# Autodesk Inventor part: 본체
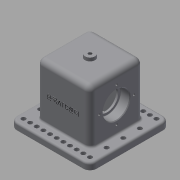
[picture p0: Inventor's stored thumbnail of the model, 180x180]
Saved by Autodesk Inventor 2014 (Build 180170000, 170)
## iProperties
Created: 2018-11
Part Number: 본체
Material: Generic
Document SubType Name: Modeling
Designer: kh
Density: 1 g/cm^3
Appearance: Default
Author: kh
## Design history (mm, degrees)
sketch "스케치1"
  geometry: L1 (60, 60)-(-60, 60); L2 (-60, 60)-(-60, -60); L3 (-60, -60)-(60, -60); L4 (60, -60)-(60, 60); L5 (60, 60)-(-60, -60); L6 (-60, 60)-(60, -60); 1 further point
  constraints: 12 end point, 2 midpoint, 2 parallel, 1 horizontal, 1 perpendicular
  dimensions: "d0" = 120 distance of L3.end L2.end; "d1" = 120 distance of L2.end L1.end
extrude "돌출1" new body sketch "스케치1" distance "d2" = 10; taper "d3" = 0 deg
sketch "스케치2"
  geometry: L1 (-40, -40)-(40, -40); L2 (40, -40)-(40, 40); L3 (40, 40)-(-40, 40); L4 (-40, 40)-(-40, -40); L5 (-40, -40)-(40, 40); L6 (40, -40)-(-40, 40); 1 further point
  constraints: 12 end point, 2 midpoint, 2 parallel, 1 horizontal, 1 perpendicular
  dimensions: "d4" = 80 distance of L3.end L2.end; "d5" = 80 distance of L2.end L1.end
extrude "돌출2" join sketch "스케치2" distance "d6" = 80; taper "d7" = 0 deg
sketch "스케치3"
  geometry: L1 (-23, -30)-(23, -30); L2 (23, -30)-(23, 30); L3 (23, 30)-(-23, 30); L4 (-23, 30)-(-23, -30); L5 (-23, -30)-(23, 30); L6 (23, -30)-(-23, 30); 1 further point
  constraints: 12 end point, 2 midpoint, 2 parallel, 1 horizontal, 1 perpendicular
  dimensions: "d8" = 46 distance of L3.end L2.end; "d9" = 60 distance of L2.end L1.end
extrude "돌출3" cut sketch "스케치3" distance "d10" = 80; taper "d11" = 0 deg
sketch "스케치4"
  geometry: L1 (23, 0)-(-23, 0) reference; L2 (-23, 0)-(23, 0) reference; L3 (-60, 0)-(60, 0) reference; L4 (60, 0)-(-60, 0) reference; L5 (-40, 90)-(40, 90) reference; L6 (40, 90)-(-40, 90) reference; L7 (-40, 48)-(40, 48); L8 (40, 68)-(26, 68); L9 (26, 68)-(26, 64.5); L10 (23, 0)-(23, 80) reference; L11 (23, 0)-(23, 80) reference; L12 (26, 64.5)-(23, 64.5); L13 (40, 68)-(40, 48); L14 (23, 64.5)-(23, 48); 1 further point
  constraints: 12 end point, 3 perpendicular, 3 point on line, 2 parallel
  dimensions: "d12" = 48 distance between parallel lines of L1 L7; "d13" = 33 diameter of L12 L7; "d14" = 40 diameter of L8 L7; "d15" = 14 distance of L8.start L8.end; "d16" = 3 distance of L9.end L12.end
revolve "회전1" sketch "스케치4" stored, may be unused: angle "d17" = 90 deg
node "작업 평면1"
sketch "스케치5"
  geometry: C1 r 7.5 at (0, 0); 2 further points
  constraints: 2 coincident, 1 centre point
  dimensions: "d19" = 15 diameter of C1
extrude "돌출4" join sketch "스케치5" stored distance "d20" = 80; taper "d21" = 0 deg
hole "구멍1" diameter "d24" = 4.917; stored, may be unused: countersink angle "d28" = 90 deg, drill point angle "d30" = 118 deg; dims "d25" = 20, "d26" = 4, "d27" = 2, "d29" = 8, "d71" = 10, "d72" = 10
sketch "스케치6"
  geometry: L1 (40, 64)-(40, 12); L2 (66, 38)-(14, 38); C1 r 20 at (40, 38) reference; A1 r 26 centre (40, 38) between (40, 64) and (40, 12); 7 further points
  constraints: 7 coincident, 4 end point, 4 point on circle, 2 midpoint, 1 centre point, 1 perpendicular, 1 vertical
  dimensions: "d31" = 52 diameter of A1
hole "구멍2" sketch "스케치6" at (40, 64), (14, 38), (40, 12), (66, 38) diameter "d32" = 3.242; stored, may be unused: countersink angle "d36" = 90 deg, drill point angle "d38" = 118 deg; dims "d33" = 8, "d34" = 4, "d35" = 2, "d37" = 10
fillet "모깎기1" dims "d39" = 10
sketch "스케치7"
  geometry: C1 r 3.3 at (50, -50); C2 r 3.3 at (-50, 50); A1 r 10 centre (50, -50) between (50, -60) and (60, -50) reference; A2 r 10 centre (-50, 50) between (-50, 60) and (-60, 50) reference; 1 further point
  constraints: 2 centre point, 2 coincident
  dimensions: "d40" = 6.6 diameter of C1; "d52" = 6.6 diameter of C2
extrude "돌출5" cut sketch "스케치7" stored distance "d41" = 80; taper "d42" = 0 deg
extrude "돌출6" cut sketch "스케치7" stored distance "d53" = 80; taper "d54" = 0 deg
fillet "모깎기2" dims "d61" = 8
fillet "모깎기3" dims "d62" = 0.6
chamfer "모따기1" distance "d63" = 1; stored, may be unused: second distance "d64" = 2, angle "d65" = 45 deg
fillet "모깎기5" dims "d67" = 3
node "작업 평면3"
fillet "모깎기6" dims "d73" = 8
fillet "모깎기7" dims "d74" = 3
sketch "스케치8"
  geometry: L1 (7.308, -27.022)-(56.692, -27.022); L2 (56.692, -27.022)-(56.692, -50.978); L3 (56.692, -50.978)-(7.308, -50.978); L4 (7.308, -50.978)-(7.308, -27.022); L5 (56.692, -27.022)-(7.308, -50.978); L6 (85.3, -87)-(78.7, -87) reference; L7 (75.3, -87)-(68.7, -87) reference; L8 (65.3, -87)-(58.7, -87) reference; L9 (55.3, -87)-(48.7, -87) reference; L10 (45.3, -87)-(38.7, -87) reference; L11 (35.3, -87)-(28.7, -87) reference; L12 (25.3, -87)-(18.7, -87) reference; L13 (15.3, -87)-(8.7, -87) reference; L14 (5.3, -87)-(-1.3, -87) reference; L15 (-4.7, -87)-(-11.3, -87) reference; L16 (-14.7, -87)-(-21.3, -87) reference; L17 (-14.7, -87)-(-21.3, -87) reference; L18 (-14.7, -87)-(-21.3, -87) reference; L19 (-14.7, -87)-(-21.3, -87) reference; L20 (85.3, -87)-(78.7, -87) reference; L21 (85.3, -87)-(78.7, -87) reference; L22 (85.3, -87)-(78.7, -87) reference; L23 (-14.7, -87)-(-21.3, -87) reference; L24 (-4.7, -87)-(-11.3, -87) reference; L25 (5.3, -87)-(-1.3, -87) reference; L26 (15.3, -87)-(8.7, -87) reference; L27 (25.3, -87)-(18.7, -87) reference; L28 (35.3, -87)-(28.7, -87) reference; L29 (45.3, -87)-(38.7, -87) reference; L30 (55.3, -87)-(48.7, -87) reference; L31 (65.3, -87)-(58.7, -87) reference; L32 (75.3, -87)-(68.7, -87) reference; L33 (85.3, -87)-(78.7, -87) reference; L34 (-18, -87)-(-28, -87) reference; L35 (82, -87)-(-18, -87) reference; L36 (92, -87)-(82, -87) reference; L37 (82, -87)-(92, -87) reference; L38 (-18, -87)-(82, -87) reference; L39 (-28, -87)-(-18, -87) reference; L40 (52, -87)-(55, -87) reference; L41 (52, -87)-(12, -87) reference; L42 (9, -87)-(12, -87) reference; L43 (12, -87)-(9, -87) reference; L44 (12, -87)-(52, -87) reference; L45 (55, -87)-(52, -87) reference; L46 (32, -87)-(32, -39)
  constraints: 4 end point, 2 midpoint, 2 other
  dimensions: "d75" = 48 distance of L46.start L46.end
feature "엠보싱1" sketch "스케치8" dims "d0" = 120, "d1" = 120, "d69" = 0.5, "d70" = 0
node "솔리드1"
mirror "대칭1"
mirror "대칭2"
pattern_linear "직사각형 패턴1" dims "d45" = 10, "d48" = 25
pattern_linear "직사각형 패턴2" dims "d51" = 25
pattern_linear "직사각형 패턴3" dims "d57" = 25
pattern_linear "직사각형 패턴4" dims "d60" = 10
node "투영된 루프1"
node "투영된 루프2"
node "투영된 루프3"
node "투영된 루프4"
other parameters: "d18" = 5
